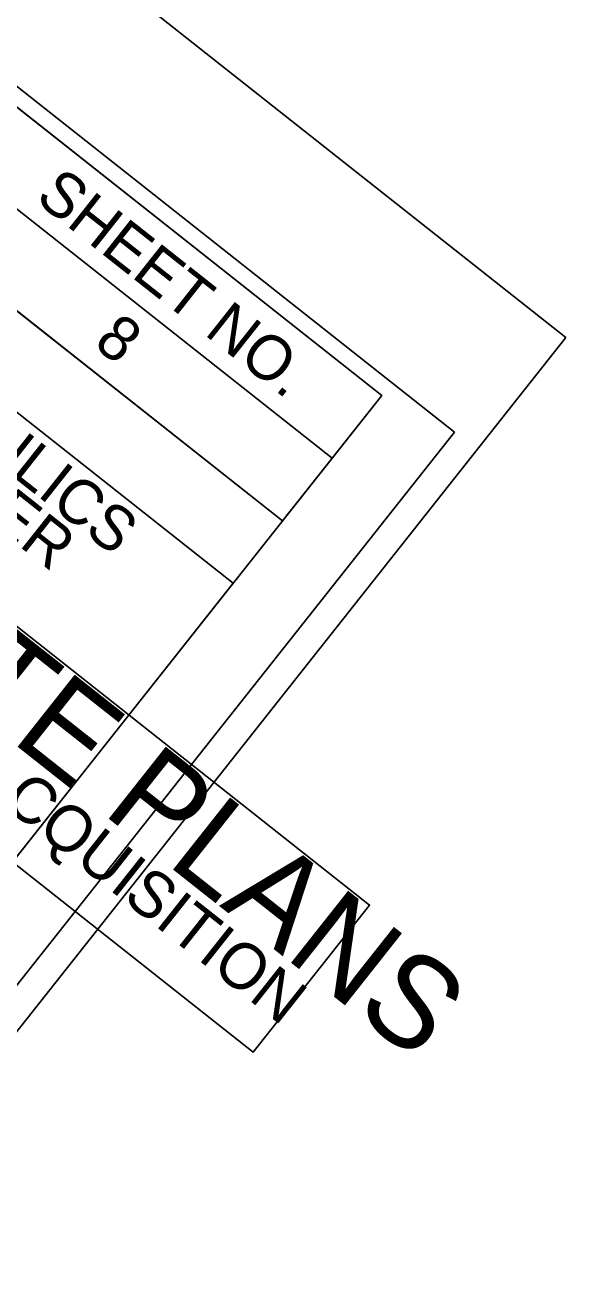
# Model space of a CAD drawing. Extents: x 557005 to 559009, y 505746 to 507841.
# Drawn here: x 558923.8 to 559008.5, y 506648.8 to 506845.2 of the extents above; entities that cross this region are included whole.
import ezdxf

# ---------------------------------------------------------------- set-up
doc = ezdxf.new("R2010")
doc.units = 0
for name, color, linetype in [('Sheet Border Standard 30in CELL', 7, 'Continuous'), ('Sheet Cutting Line CELL', 7, 'Continuous'), ('Sheet Data Field CELL', 7, 'Continuous'), ('Sheet Plot Border Inside CELL', 7, 'Continuous'), ('Sheet Plot Border Outside CELL', 7, 'Continuous'), ('Sheet Sticker Incomplete CELL', 7, 'Continuous')]:
    doc.layers.add(name, color=color, linetype=linetype)

msp = doc.modelspace()

# ---------------------------------------------------------------- linework, layer by layer
at = {"layer": 'Sheet Border Standard 30in CELL'}
for p, q in [((558814.98, 506901.37), (558971.9, 506777.29)), ((558807.23, 506891.56), (558964.15, 506767.48)), ((558807.23, 506891.56), (558964.15, 506767.48))]:
    msp.add_line(p, q, dxfattribs=at)
for points in [[(558979.69, 506787.13), (557803.06, 507717.49), (557151.81, 506893.85), (558328.44, 505963.5)], [(558822.76, 506911.21), (558979.69, 506787.13), (558964.15, 506767.48), (558807.23, 506891.56)], [(558877.95, 506819.7), (558956.4, 506757.68), (558886.62, 506669.43), (558808.18, 506731.46)]]:
    msp.add_lwpolyline(points, close=True, dxfattribs=at)
at = {"layer": 'Sheet Cutting Line CELL'}
msp.add_line((559008.53, 506796.2), (557687.57, 507840.68), dxfattribs=at)
at = {"layer": 'Sheet Plot Border Inside CELL'}
msp.add_lwpolyline([(558991.07, 506781.38), (557683.84, 507815), (557029.43, 506987.37), (558336.66, 505953.74)], close=True, dxfattribs=at)
at = {"layer": 'Sheet Plot Border Outside CELL'}
msp.add_lwpolyline([(559008.53, 506796.2), (557687.57, 507840.68), (557005.31, 506977.82), (558326.27, 505933.34)], close=True, dxfattribs=at)
at = {"layer": 'Sheet Sticker Incomplete CELL'}
msp.add_lwpolyline([(558815.43, 506798.18), (558833.65, 506821.22), (558977.78, 506707.25), (558959.56, 506684.21)], close=True, dxfattribs=at)

# ---------------------------------------------------------------- texts
at = {"layer": 'Sheet Border Standard 30in CELL'}
for s, p in [('SHEET NO.', (558925.21, 506817.72)), ('HYDRAULICS', (558890.47, 506799.23)), ('ENGINEER', (558889.66, 506789.73))]:
    msp.add_text(s, height=7, rotation=321.6667, dxfattribs=at).set_placement(p)
at = {"layer": 'Sheet Data Field CELL'}
msp.add_text('8', height=7, rotation=321.6667, dxfattribs=at).set_placement((558934.34, 506794.94))
at = {"layer": 'Sheet Sticker Incomplete CELL'}
for s, height, p in [('INCOMPLETE PLANS', 14.4, (558833.3, 506802.71)), ('DO NOT USE FOR R/W ACQUISITION', 7.2, (558831.09, 506793.38))]:
    msp.add_text(s, height=height, rotation=321.6667, dxfattribs=at).set_placement(p)

doc.saveas('drawing.dxf')
